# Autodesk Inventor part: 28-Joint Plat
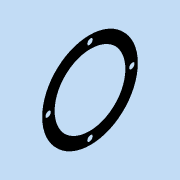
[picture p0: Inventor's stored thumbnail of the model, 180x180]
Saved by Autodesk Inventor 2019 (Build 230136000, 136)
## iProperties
Created: 2023-02
Part Number: 28-Joint Plat
Material: Générique
Document SubType Name: Modeling
Designer: Thier
Density: 1 g/cm^3
Appearance: Anodisé - Noir
Author: Thier
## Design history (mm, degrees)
sketch "Esquisse1"
  geometry: C1 r 36 at (0, 0); C2 r 47.5 at (0, 0); 1 further point
  constraints: 2 centre point, 2 coincident
  dimensions: "d0" = 95 diameter of C2; "d1" = 72 diameter of C1
extrude "Extrusion1" new body sketch "Esquisse1" distance "d2" = 1; taper "d3" = 0 deg
sketch "Esquisse2"
  geometry: C1 r 36 at (0, 0) reference; 2 further points
  dimensions: "d11" = 42 distance of C1.centre point (0, 42); "d12" = 0 horizontal distance of C1.centre point (0, 42)
hole "Perçage1" sketch "Esquisse2" at (0, 42) diameter "d4" = 6.2; stored, may be unused: countersink angle "d8" = 90 deg, drill point angle "d10" = 118 deg; dims "d5" = 6, "d6" = 4, "d7" = 2, "d9" = 8
pattern_circular "Réseau circulaire1" dims angle "d14" = 360 deg
node "Solide1"
